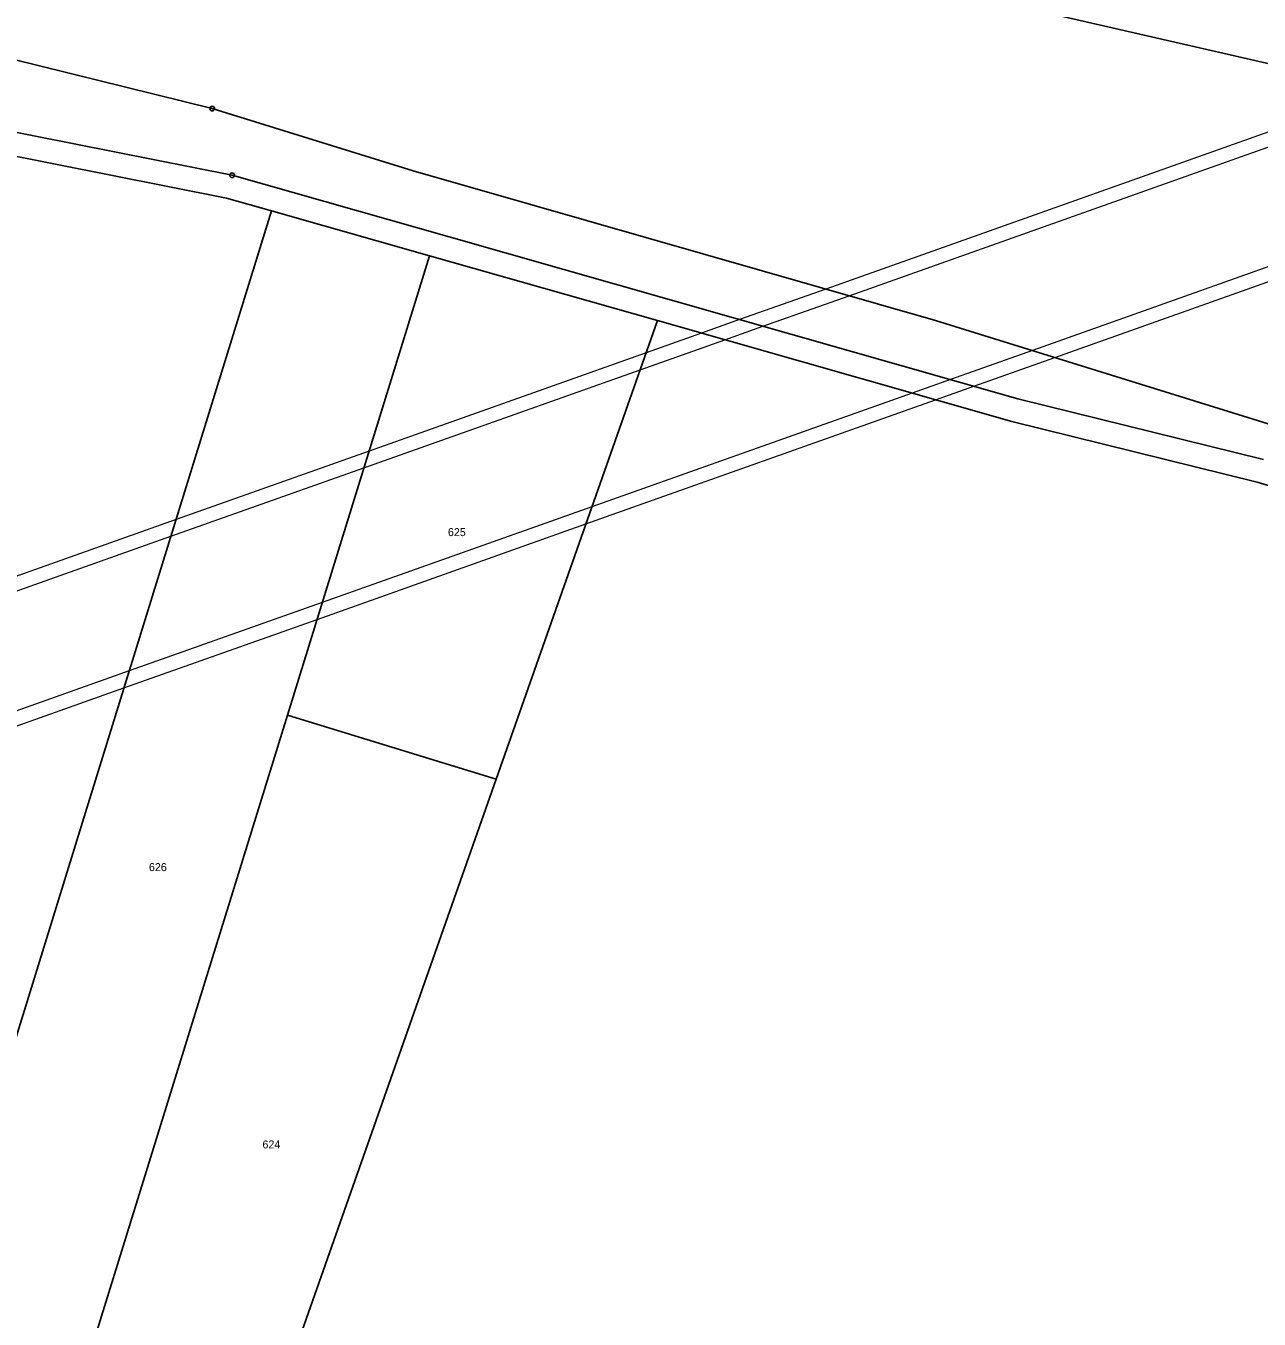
# Model space of a CAD drawing. Extents: x -759947 to -757003, y -1019641 to -1017100.
# Drawn here: x -759227.1 to -758964.9, y -1018952.6 to -1018677.9 of the extents above; entities that cross this region are included whole.
import ezdxf

# ---------------------------------------------------------------- set-up
doc = ezdxf.new("R2010")
doc.units = 0
doc.header["$LTSCALE"] = 0.68
for name, color, linetype, lineweight in [('1', 7, 'Continuous', 25), ('13', 7, 'Continuous', 13), ('8', 7, 'Continuous', 25)]:
    doc.layers.add(name, color=color, linetype=linetype, lineweight=lineweight)
doc.layers.add('2', color=7, linetype='Continuous')

msp = doc.modelspace()

# ---------------------------------------------------------------- linework, layer by layer
at = {"layer": '1'}
for p, q in [((-759085.07, -1018657.87), (-758959.96, -1018686.53)), ((-759230.15, -1018684.87), (-759187.43, -1018695.44)), ((-759187.43, -1018695.44), (-759144.74, -1018708.69)), ((-759183.22, -1018709.59), (-759243.35, -1018697.69)), ((-759243.96, -1018702.67), (-759184.39, -1018714.46)), ((-759137.09, -1018722.7), (-759183.22, -1018709.59)), ((-759144.74, -1018708.69), (-759033.69, -1018740.44)), ((-759184.39, -1018714.46), (-759174.84, -1018717.17)), ((-759174.84, -1018717.17), (-759216.51, -1018851.88)), ((-759174.84, -1018717.17), (-759141.27, -1018726.71)), ((-759016.24, -1018757.08), (-759137.09, -1018722.7)), ((-759141.27, -1018726.71), (-759171.46, -1018824.32)), ((-759141.27, -1018726.71), (-759092.82, -1018740.49)), ((-759127.1, -1018837.92), (-759092.82, -1018740.49)), ((-759092.82, -1018740.49), (-759017.52, -1018761.91)), ((-759033.69, -1018740.44), (-758962.06, -1018762.66)), ((-758964.01, -1018769.96), (-759016.24, -1018757.08)), ((-759017.52, -1018761.91), (-758965.33, -1018774.78)), ((-758965.33, -1018774.78), (-758957.04, -1018777.3)), ((-759223.95, -1018993.99), (-759171.46, -1018824.32)), ((-759171.46, -1018824.32), (-759127.1, -1018837.92)), ((-759127.1, -1018837.92), (-759184.98, -1019002.42)), ((-759216.51, -1018851.88), (-759258.18, -1018986.59))]:
    msp.add_line(p, q, dxfattribs=at)
at = {"layer": '13'}
for points in [[(-758931.32, -1018689.16), (-759057.03, -1018733.77), (-759052.08, -1018735.18), (-758932.76, -1018692.86)], [(-758944.27, -1018722.43), (-759013.08, -1018746.83), (-759008.31, -1018748.31), (-758945.93, -1018726.18)], [(-759057.03, -1018733.77), (-759075.35, -1018740.26), (-759083.48, -1018743.15), (-759078.51, -1018744.56), (-759070.39, -1018741.68), (-759052.08, -1018735.18)], [(-759096.5, -1018750.94), (-759078.51, -1018744.56), (-759083.48, -1018743.15), (-759095.22, -1018747.31)], [(-759013.08, -1018746.83), (-759030.52, -1018753.02), (-759038.65, -1018755.9), (-759033.68, -1018757.31), (-759025.56, -1018754.43), (-759008.31, -1018748.31)], [(-759155.2, -1018771.76), (-759096.5, -1018750.94), (-759095.22, -1018747.31), (-759154.1, -1018768.21)], [(-759108.02, -1018783.69), (-759033.68, -1018757.31), (-759038.65, -1018755.9), (-759106.74, -1018780.04)], [(-759195.13, -1018782.76), (-759196.23, -1018786.31), (-759155.2, -1018771.76), (-759154.1, -1018768.21)], [(-759165.16, -1018803.96), (-759108.02, -1018783.69), (-759106.74, -1018780.04), (-759164.05, -1018800.37)], [(-759195.13, -1018782.76), (-759290.45, -1018816.58), (-759312.64, -1018824.45), (-759313.49, -1018827.9), (-759289.43, -1018819.37), (-759196.23, -1018786.31)], [(-759206.19, -1018818.52), (-759165.16, -1018803.96), (-759164.05, -1018800.37), (-759205.08, -1018814.92)], [(-759205.08, -1018814.92), (-759281.41, -1018841.99), (-759320.35, -1018855.8), (-759321.22, -1018859.33), (-759280.35, -1018844.83), (-759206.19, -1018818.52)]]:
    msp.add_lwpolyline(points, close=True, dxfattribs=at)
at = {"layer": '8'}
for centre, radius in [((-759187.43, -1018695.4399), 0.5), ((-759187.43, -1018695.4399), 0.0303), ((-759183.22, -1018709.5899), 0.5), ((-759183.22, -1018709.5899), 0.0303)]:
    msp.add_circle(centre, radius, dxfattribs=at)

# ---------------------------------------------------------------- texts
at = {"layer": '2'}
for s, p in [('625', (-759137.34, -1018786.265)), ('626', (-759200.89, -1018857.445)), ('624', (-759176.76, -1018916.365))]:
    msp.add_text(s, height=1.7, dxfattribs=at).set_placement(p)

doc.saveas('drawing.dxf')
